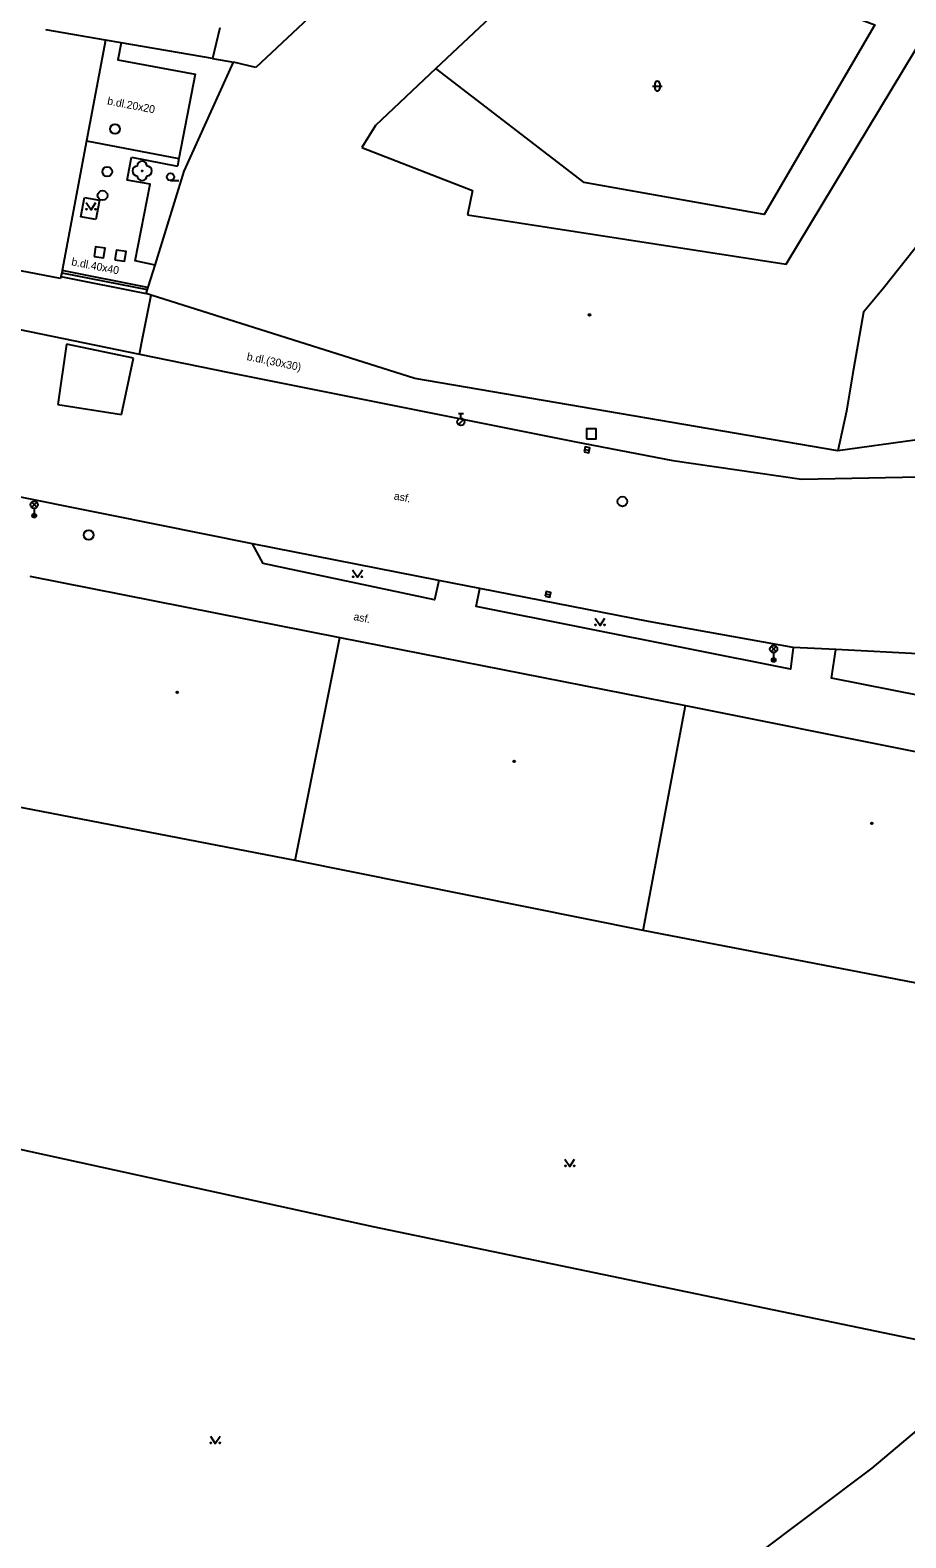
# Model space of a CAD drawing. Extents: x -599770 to -598493, y -1162076 to -1159209.
# Drawn here: x -599063.1 to -599018.2, y -1161484.3 to -1161406.9 of the extents above; entities that cross this region are included whole.
import ezdxf

# ---------------------------------------------------------------- set-up
doc = ezdxf.new("R2010")
doc.units = 0
doc.layers.add('Podklad', color=7, linetype='Continuous')

msp = doc.modelspace()

# ---------------------------------------------------------------- linework, layer by layer
at = {"layer": 'Podklad'}
for p, q in [((-599031.068, -1161409.693), (-599031.068, -1161409.943)), ((-599030.818, -1161409.693), (-599030.818, -1161409.943)), ((-599031.193, -1161409.818), (-599030.693, -1161409.818)), ((-599055.9, -1161414.668), (-599055.462, -1161414.668)), ((-599041.135, -1161426.613), (-599040.885, -1161426.613)), ((-599041.01, -1161426.863), (-599041.01, -1161426.613)), ((-599041.139, -1161427.186), (-599040.874, -1161426.921)), ((-599034.673, -1161428.455), (-599034.427, -1161428.505)), ((-599063.012, -1161431.43), (-599062.747, -1161431.165)), ((-599063.012, -1161431.165), (-599062.747, -1161431.43)), ((-599062.88, -1161431.485), (-599062.88, -1161431.86)), ((-599036.673, -1161435.865), (-599036.427, -1161435.915)), ((-599025.113, -1161438.83), (-599024.848, -1161438.565)), ((-599025.113, -1161438.565), (-599024.848, -1161438.83)), ((-599024.98, -1161438.885), (-599024.98, -1161439.26))]:
    msp.add_line(p, q, dxfattribs=at)
for points in [[(-599041.83, -1161399.77), (-599051.53, -1161408.86)], [(-599036.2, -1161403.17), (-599034.62, -1161404.76), (-599032.59, -1161401.87), (-599019.79, -1161406.67), (-599025.47, -1161416.41), (-599034.69, -1161414.77), (-599042.3, -1161408.91)], [(-599036.2, -1161403.17), (-599042.3, -1161408.91)], [(-599059.22, -1161407.46), (-599062.29, -1161406.93)], [(-599059.22, -1161407.46), (-599060.2, -1161412.63), (-599061.45, -1161419.28), (-599061.47, -1161419.4), (-599061.51, -1161419.59), (-599061.53, -1161419.69)], [(-599053.75, -1161408.41), (-599058.43, -1161407.6), (-599059.22, -1161407.46)], [(-599053.36, -1161406.83), (-599053.75, -1161408.41)], [(-599024.33, -1161418.96), (-599017.11, -1161406.97)], [(-599058.43, -1161407.6), (-599058.59, -1161408.47), (-599054.64, -1161409.2), (-599055.47, -1161413.53), (-599055.54, -1161413.92)], [(-599055.2, -1161414.18), (-599052.67, -1161408.6)], [(-599053.75, -1161408.41), (-599052.67, -1161408.6)], [(-599051.53, -1161408.86), (-599052.67, -1161408.6)], [(-599042.3, -1161408.91), (-599045.38, -1161411.84)], [(-599045.38, -1161411.84), (-599046.09, -1161412.97)], [(-599060.2, -1161412.63), (-599055.47, -1161413.53)], [(-599058.11, -1161414.64), (-599057.89, -1161413.47)], [(-599057.89, -1161413.47), (-599055.54, -1161413.92)], [(-599046.09, -1161412.97), (-599040.42, -1161415.17)], [(-599057.14, -1161420.46), (-599056.69, -1161419.01), (-599055.2, -1161414.18)], [(-599056.69, -1161419.01), (-599057.7, -1161418.78), (-599056.94, -1161414.85), (-599058.11, -1161414.64)], [(-599040.42, -1161415.17), (-599040.67, -1161416.42)], [(-599060.5, -1161416.52), (-599060.31, -1161415.53)], [(-599060.5, -1161416.52), (-599060.31, -1161415.53)], [(-599060.31, -1161415.53), (-599059.53, -1161415.68)], [(-599060.31, -1161415.53), (-599059.53, -1161415.68)], [(-599060.22, -1161415.785), (-599059.97, -1161416.16), (-599059.72, -1161415.785)], [(-599059.53, -1161415.68), (-599059.72, -1161416.67)], [(-599059.53, -1161415.68), (-599059.72, -1161416.67)], [(-599061.53, -1161419.69), (-599066.1, -1161418.82), (-599069.2, -1161418.24), (-599072.92, -1161417.52), (-599080.69, -1161416.12)], [(-599059.72, -1161416.67), (-599060.5, -1161416.52)], [(-599059.72, -1161416.67), (-599060.5, -1161416.52)], [(-599040.67, -1161416.42), (-599024.33, -1161418.96)], [(-599016.28, -1161416.3), (-599019.35, -1161420.18)], [(-599081.48, -1161419), (-599073.27, -1161420.41), (-599071.29, -1161420.77), (-599064.79, -1161422.07), (-599057.48, -1161423.57), (-599052.89, -1161424.52), (-599035.2, -1161428.06)], [(-599061.51, -1161419.59), (-599057.14, -1161420.46)], [(-599061.47, -1161419.4), (-599057.1, -1161420.26)], [(-599057.08, -1161420.15), (-599061.45, -1161419.28)], [(-599057.48, -1161423.57), (-599057.36, -1161422.94), (-599056.89, -1161420.54)], [(-599043.38, -1161424.82), (-599056.89, -1161420.54), (-599057.14, -1161420.46)], [(-599057.1, -1161420.26), (-599057.08, -1161420.15)], [(-599057.1, -1161420.26), (-599057.08, -1161420.15)], [(-599019.35, -1161420.18), (-599020.38, -1161421.41)], [(-599020.38, -1161421.41), (-599020.93, -1161424.64)], [(-599061.23, -1161423.06), (-599061.67, -1161426.16)], [(-599057.79, -1161423.77), (-599061.23, -1161423.06)], [(-599058.4, -1161426.66), (-599057.79, -1161423.77)], [(-599021.69, -1161428.53), (-599043.38, -1161424.82)], [(-599020.93, -1161424.64), (-599021.25, -1161426.5)], [(-599051.69, -1161433.3), (-599059.07, -1161431.81), (-599070.51, -1161429.53), (-599074.61, -1161428.71), (-599081.96, -1161427.25), (-599084.95, -1161426.71)], [(-599061.67, -1161426.16), (-599058.4, -1161426.66)], [(-599021.25, -1161426.5), (-599021.69, -1161428.53)], [(-599007.76, -1161426.57), (-599017.75, -1161427.98), (-599021.69, -1161428.53)], [(-599035.2, -1161428.06), (-599030.15, -1161429.02), (-599023.56, -1161429.98), (-599017.52, -1161429.87)], [(-599042.15, -1161435.18), (-599051.69, -1161433.3)], [(-599042.15, -1161435.18), (-599042.36, -1161436.18), (-599051.14, -1161434.32), (-599051.69, -1161433.3)], [(-599063.11, -1161434.97), (-599047.21, -1161438.1)], [(-599046.56, -1161434.645), (-599046.31, -1161435.02), (-599046.06, -1161434.645)], [(-599040.04, -1161435.59), (-599042.15, -1161435.18)], [(-599023.98, -1161438.62), (-599024.12, -1161439.73), (-599040.22, -1161436.52), (-599040.04, -1161435.59)], [(-599023.98, -1161438.62), (-599031.39, -1161437.29), (-599040.04, -1161435.59)], [(-599034.13, -1161437.115), (-599033.88, -1161437.49), (-599033.63, -1161437.115)], [(-599049.5, -1161449.55), (-599047.21, -1161438.1)], [(-599047.21, -1161438.1), (-599029.5, -1161441.59)], [(-599021.8, -1161438.73), (-599023.98, -1161438.62)], [(-599005.47, -1161439.03), (-599006.33, -1161443.27), (-599017.35, -1161441.11), (-599022.02, -1161440.2), (-599021.8, -1161438.73)], [(-599005.47, -1161439.03), (-599012.51, -1161439.2), (-599017.27, -1161438.96), (-599021.8, -1161438.73)], [(-599031.67, -1161453.14), (-599029.5, -1161441.59)], [(-599029.5, -1161441.59), (-599017.9, -1161443.92), (-599011.15, -1161445.27)], [(-599049.5, -1161449.55), (-599064.46, -1161446.66)], [(-599031.67, -1161453.14), (-599049.5, -1161449.55)], [(-599013.57, -1161456.62), (-599031.67, -1161453.14)], [(-599066.67, -1161463.69), (-599045.52, -1161468.32)], [(-599035.68, -1161464.865), (-599035.43, -1161465.24), (-599035.18, -1161464.865)], [(-599045.52, -1161468.32), (-599013.21, -1161475.04)], [(-599013.21, -1161475.04), (-599019.94, -1161480.72), (-599029.22, -1161487.7), (-599044.14, -1161496.19), (-599078.19, -1161511.59), (-599082.25, -1161512.54), (-599085.11, -1161512.99), (-599086.46, -1161512.67)], [(-599053.85, -1161479.075), (-599053.6, -1161479.45), (-599053.35, -1161479.075)]]:
    msp.add_lwpolyline(points, dxfattribs=at)
for points in [[(-599059.816, -1161418.558), (-599059.322, -1161418.636), (-599059.244, -1161418.142), (-599059.738, -1161418.064)], [(-599058.746, -1161418.728), (-599058.252, -1161418.806), (-599058.174, -1161418.312), (-599058.668, -1161418.234)], [(-599034.58, -1161427.91), (-599034.08, -1161427.91), (-599034.08, -1161427.41), (-599034.58, -1161427.41)], [(-599034.697, -1161428.578), (-599034.452, -1161428.627), (-599034.403, -1161428.382), (-599034.648, -1161428.333)], [(-599036.697, -1161435.988), (-599036.452, -1161436.037), (-599036.403, -1161435.792), (-599036.648, -1161435.743)]]:
    msp.add_lwpolyline(points, close=True, dxfattribs=at)
for centre, radius in [((-599058.74, -1161412.02), 0.25), ((-599059.14, -1161414.21), 0.25), ((-599057.35, -1161414.17), 0.025), ((-599055.9, -1161414.48), 0.188), ((-599059.38, -1161415.43), 0.25), ((-599060.195, -1161416.135), 0.025), ((-599059.745, -1161416.135), 0.025), ((-599034.42, -1161421.56), 0.045), ((-599034.42, -1161421.56), 0.0199), ((-599041.01, -1161427.05), 0.188), ((-599062.88, -1161431.297), 0.188), ((-599032.73, -1161431.13), 0.25), ((-599062.88, -1161431.86), 0.1), ((-599062.88, -1161431.86), 0.0723), ((-599062.88, -1161431.86), 0.0438), ((-599060.09, -1161432.85), 0.25), ((-599046.535, -1161434.995), 0.025), ((-599046.085, -1161434.995), 0.025), ((-599034.105, -1161437.465), 0.025), ((-599033.655, -1161437.465), 0.025), ((-599024.98, -1161438.698), 0.188), ((-599024.98, -1161439.26), 0.1), ((-599024.98, -1161439.26), 0.0723), ((-599024.98, -1161439.26), 0.0438), ((-599055.55, -1161440.92), 0.045), ((-599055.55, -1161440.92), 0.0199), ((-599038.28, -1161444.46), 0.045), ((-599038.28, -1161444.46), 0.0199), ((-599019.95, -1161447.64), 0.045), ((-599019.95, -1161447.64), 0.0199), ((-599035.655, -1161465.215), 0.025), ((-599035.205, -1161465.215), 0.025), ((-599053.825, -1161479.425), 0.025), ((-599053.375, -1161479.425), 0.025)]:
    msp.add_circle(centre, radius, dxfattribs=at)
for centre, radius, start, end in [((-599030.943, -1161409.693), 0.125, 0, 180), ((-599030.943, -1161409.943), 0.125, 180, 0), ((-599057.35, -1161413.92), 0.25, 0, 180), ((-599057.6, -1161414.17), 0.25, 90, 270), ((-599057.35, -1161414.42), 0.25, 180, 0), ((-599057.1, -1161414.17), 0.25, 270, 90)]:
    msp.add_arc(centre, radius, start, end, dxfattribs=at)

# ---------------------------------------------------------------- texts
for s, rotation, p in [('b.dl.20x20', 349.20455, (-599059.16, -1161410.76)), ('b.dl.40x40', 349.055, (-599061, -1161419.01)), ('b.dl.(30x30)', 348.36637, (-599052.01, -1161423.87)), ('asf.', 348.85, (-599044.47, -1161431.02)), ('asf.', 348.85, (-599046.54, -1161437.21))]:
    msp.add_text(s, height=0.4, rotation=rotation, dxfattribs=at).set_placement(p)

doc.saveas('drawing.dxf')
